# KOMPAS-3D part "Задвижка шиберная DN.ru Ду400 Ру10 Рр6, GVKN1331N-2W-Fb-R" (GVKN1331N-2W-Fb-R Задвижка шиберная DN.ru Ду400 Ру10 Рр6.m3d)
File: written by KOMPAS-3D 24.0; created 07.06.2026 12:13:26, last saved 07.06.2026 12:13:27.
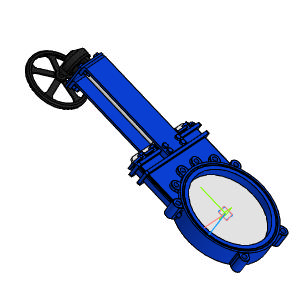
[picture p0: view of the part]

Document properties: Автор: DN.ru; Полное имя файла: E:\Работа\Зайцев\АУТСОРС\Даня\GVKN1331N-2W-Fb-R Задвижка шиберная DN.ru Ду400-600 Ру4-6\исходные материалы\DN400\DN400\GVKN1331N-2W-Fb-R Задвижка шиберная DN.ru Ду400 Ру10 Рр6.m3d

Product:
- Part/product: Задвижка шиберная DN.ru Ду400 Ру10 Рр6  | designation GVKN1331N-2W-Fb-R
    Масса: 90
    Раздел спецификации: Прочие изделия
    Примечание: D040-07578

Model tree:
1. Операция без истории:1

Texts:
  GVKN1331N-2W-Fb-R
